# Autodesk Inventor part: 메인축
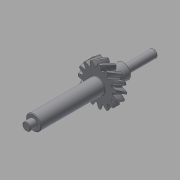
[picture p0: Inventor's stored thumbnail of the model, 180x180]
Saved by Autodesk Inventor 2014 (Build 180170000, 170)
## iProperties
Created: 2016-12
Part Number: 메인축
Material: 강철, 탄소
Document SubType Name: Modeling
Designer: mduedu
Categories: <?xml version="1.0" encoding="UTF-16"?> <MemberInstance><Categories><FamilyTemplate><FamilyTemplateParameter ValueType="xs:double" Id="1" ObjectReferenceKey="da
Density: 7.87 g/cm^3
Appearance: Default
Mass: 199.398 g
Surface Area: 86.9137 cm^2
Volume: 25.3365 cm^3
CustomPartVersion: 1
Author: mduedu
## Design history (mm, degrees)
sketch "Sketch1"
  geometry: C1 r 19.321 at (0, 0)
  constraints: 1 centre point
  dimensions: "d0" = 38.64102 diameter of C1 (= da_da)
extrude "Extrusion1" new body sketch "Sketch1" distance "d1" = 10 (= da_b); taper "d2" = 0 deg
workplane "Work Plane2"
sketch "Sketch2"
  geometry: C1 r 19.321 at (0, 0) reference; C2 r 17.321 at (0, 0)
  constraints: 1 centre point, 1 coincident
  dimensions: "d3" = 34.64102 diameter of C2 (= da_dw)
feature "피치 지름" sketch "Sketch2" dims "d4" = 10, "d5" = 0
workplane "Work Plane8"
workplane "Work Plane9"
feature "스퍼 기어" dims "da_b" = 10, "da_d" = 34.64102, "da_aw" = 43.87862, "da_da" = 38.64102, "da_df" = 29.64102, "da_dw" = 34.64102, angle "da_beta" = 30 deg, "da_lefttooth" = 0, "da_righttooth" = 10
sketch "스케치3"
  geometry: C1 r 7.5 at (0, 0); 1 further point
  constraints: 1 centre point, 1 coincident
  dimensions: "d49" = 15 diameter of C1
extrude "돌출2" join sketch "스케치3" distance "d50" = 64; taper "d51" = 0 deg
sketch "스케치4"
  geometry: C1 r 4 at (0, 0); 1 further point
  constraints: 1 centre point, 1 coincident
  dimensions: "d52" = 8 diameter of C1
extrude "돌출3" join sketch "스케치4" distance "d53" = 7; taper "d54" = 0 deg
sketch "스케치5"
  geometry: C1 r 7.5 at (0, 0) reference; 1 further point
extrude "돌출4" join sketch "스케치5" distance "d55" = 16; taper "d56" = 0 deg
sketch "스케치6"
  geometry: C1 r 4 at (0, 0); 1 further point
  constraints: 1 centre point, 1 coincident
  dimensions: "d57" = 8 diameter of C1
extrude "돌출5" join sketch "스케치6" distance "d58" = 30; taper "d59" = 0 deg
chamfer "모따기1" distance "d60" = 0.5; stored, may be unused: second distance "d61" = 2, angle "d62" = 45 deg
fillet "모깎기1" dims "d63" = 0.5
body "Solid1"
body "Srf1"
other parameters: "d16" = 43.87862 (= da_aw), "d17" = 0, "d34" = 12 deg (computed from da_z), "d39" = 0, "d41" = 0, "d43" = 43.87862 (= da_aw), "d46" = 43.87862 (= da_aw), "d47" = 0, "d48" = 0
